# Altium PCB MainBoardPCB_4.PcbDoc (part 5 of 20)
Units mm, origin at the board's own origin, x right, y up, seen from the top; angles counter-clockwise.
Board outline 333.63 x 349.38 mm, 16 copper layers (L1, L2 (GND), L3 (Sign), L4 (GND), L5 (Sign), L6 (PWR/GND), L7(PWR/GND), L8 (Plane_GND), L9 (PWR/GND), L10 (PWR/GND), L11 (PWR/GND), L12 (Sign), L13 (GND), L14 (Sign), L15 (GND), L16), stack 2.502 mm thick; 2205 components, 1648 nets, 8314 pads, 3172 vias.
Unrouted connection lines stored in the file: 5141.
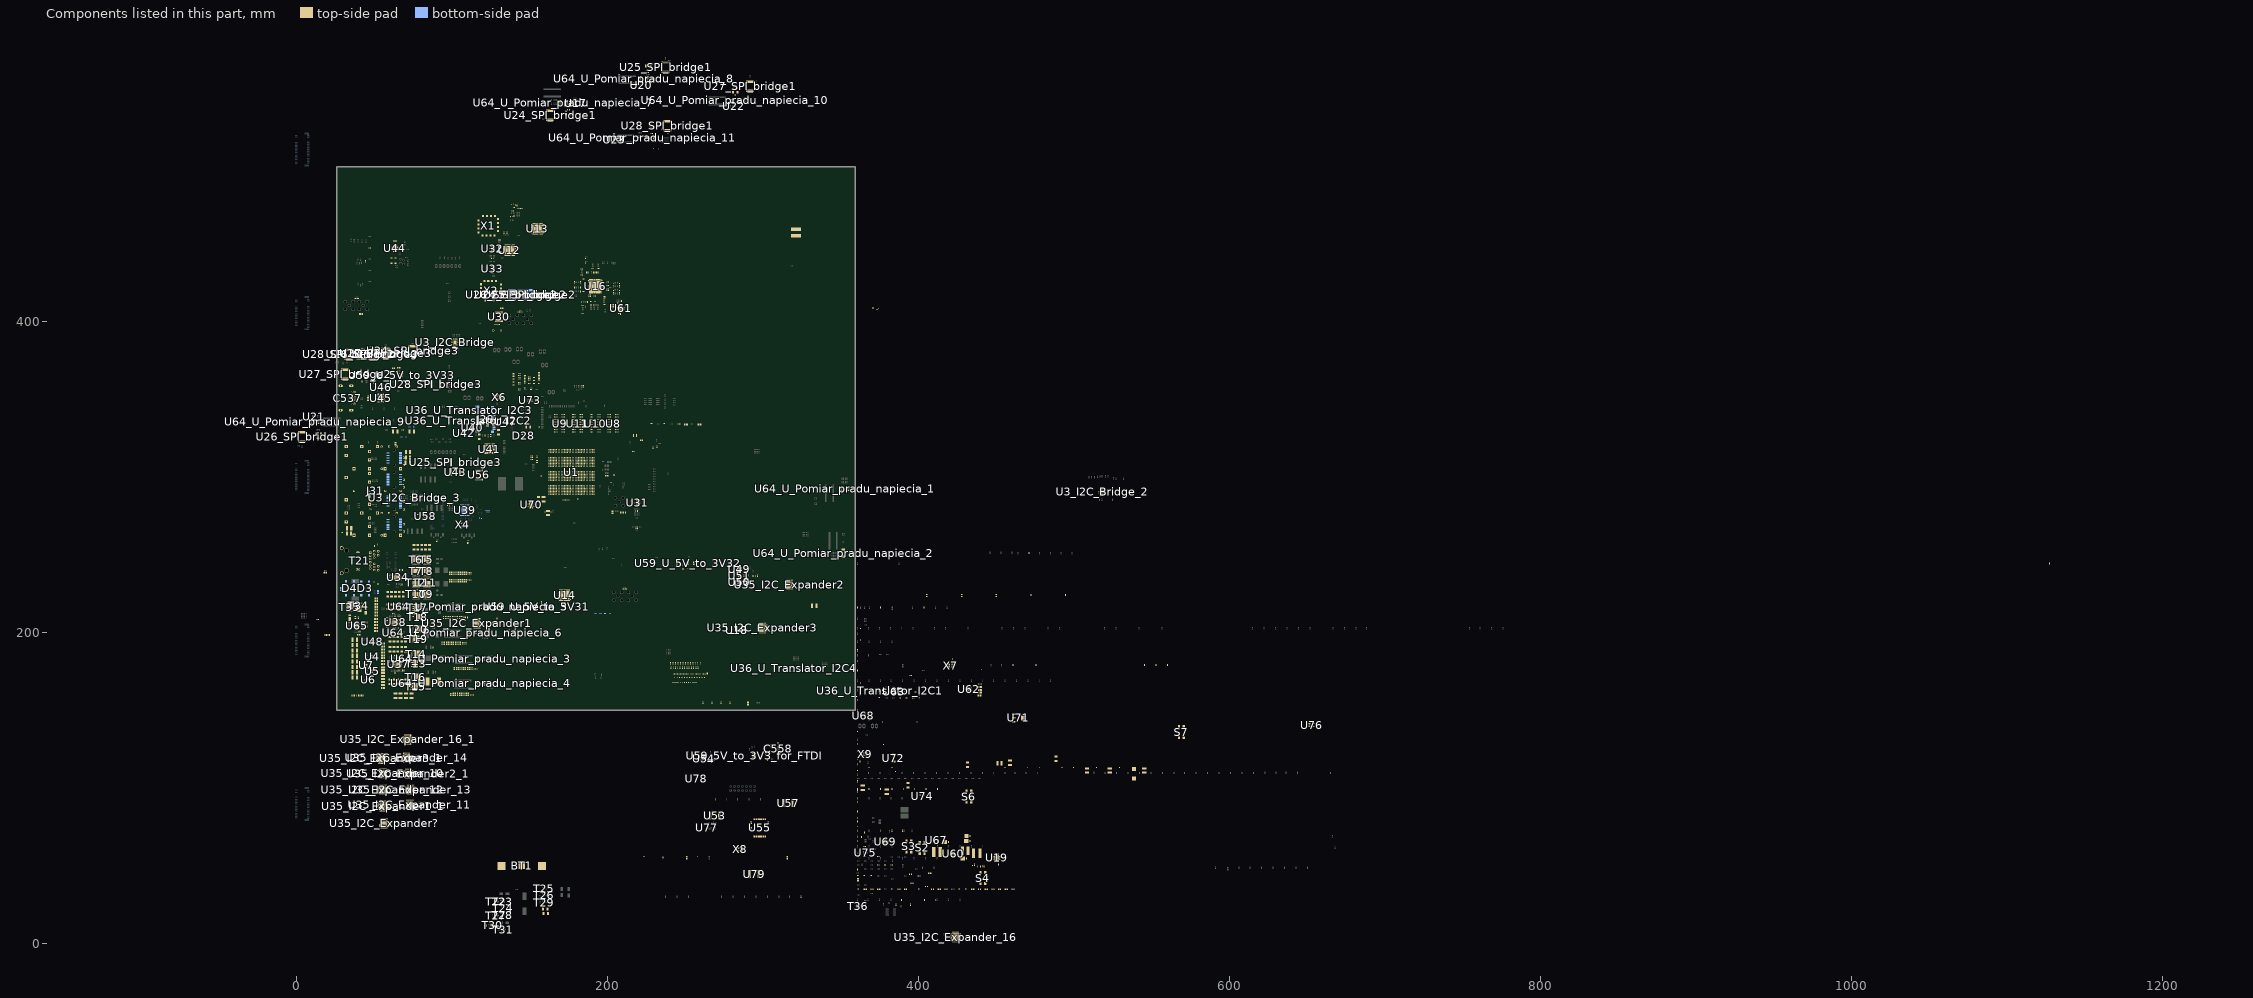
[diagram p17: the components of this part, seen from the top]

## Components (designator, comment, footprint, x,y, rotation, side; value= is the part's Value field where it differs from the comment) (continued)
T5 "BSC080N03LSG" BSC080N03LS 83.977,246.623 r90 top
T6 "BSC080N03LSG" BSC080N03LS 76.977,246.623 r90 top locked
T7 "BSC030N03LS-G" BSC030N03LS 76.977,239.389 r90 top
T8 "BSC030N03LS-G" BSC030N03LS 83.977,239.389 r90 top
T9 "BSC080N03LSG" BSC080N03LS 83.977,224.601 r270 top
T10 "BSC080N03LSG" BSC080N03LS 76.983,224.601 r270 top
T11 "BSC030N03LS-G" BSC030N03LS 83.977,231.864 r270 top
T12 "BSC030N03LS-G" BSC030N03LS 76.977,231.864 r270 top
T13 "BSC080N03LSG" BSC080N03LS 77.142,179.908 r180 top
T14 "BSC030N03LS-G" BSC030N03LS 77.114,186.055 r0 top
T15 "BSC080N03LSG" BSC080N03LS 76.889,165.106 r180 top
T16 "BSC030N03LS-G" BSC030N03LS 76.91,171.285 r0 top
T17 "BSC080N03LSG" BSC080N03LS 78.098,215.984 r180 top
T18 "BSC030N03LS-G" BSC030N03LS 78.073,209.702 r0 top
T19 "BSC080N03LSG" BSC080N03LS 78.029,195.651 r180 top
T20 "BSC030N03LS-G" BSC030N03LS 77.974,202.057 r0 top
T21 "7499511440" 7499511440 37.922,246.126 r90 bottom
T22 "IRLML6401TRPBF" IRLML6401PbF 128.638,26.733 r0 top
T23 "IRLML6401TRPBF" IRLML6401PbF 132.715,26.81 r0 top
T24 "SI2342DS-T1-GE3" SI2342DS-T1-GE3 132.905,22.581 r0 top
T25 "SI2342DS-T1-GE3" SI2342DS-T1-GE3 159.55,35.065 r0 top
T26 "SI2342DS-T1-GE3" SI2342DS-T1-GE3 159.461,30.836 r0 top
T27 "IRLML6401TRPBF" IRLML6401PbF 128.524,17.818 r0 top
T28 "SI2342DS-T1-GE3" SI2342DS-T1-GE3 132.601,18.212 r0 top
T29 "SI2342DS-T1-GE3" SI2342DS-T1-GE3 159.55,26.2 r0 top
T30 "IRLML6401TRPBF" IRLML6401PbF 126.263,11.532 r0 top
T31 "SI2342DS-T1-GE3" SI2342DS-T1-GE3 133.096,8.801 r0 top
T34 "RJK0651DPB-00#J5" RJK0651DPB 40.282,216.141 r270 top
T35 "SIJ482DP-T1-GE3" SiJ482DP 34.455,216.179 r90 top
T36 "SI2342DS-T1-GE3" SI2342DS-T1-GE3 361.423,24.028 r0 top
TP1_I2C_Bridge "TestPoint" TestPoint 766.635,73.393 r90 top (schematic designator TP1)
TP1_I2C_Bridge_2 "TestPoint" TestPoint 1231.379,242.418 r90 top (schematic designator TP1)
TP1_I2C_Bridge_3 "TestPoint" TestPoint 775.271,83.629 r90 top (schematic designator TP1)
TP2_I2C_Bridge "TestPoint" TestPoint 743.534,73.393 r90 top (schematic designator TP2)
TP2_I2C_Bridge_2 "TestPoint" TestPoint 1206.233,242.418 r90 top (schematic designator TP2)
TP2_I2C_Bridge_3 "TestPoint" TestPoint 751.662,83.629 r90 top (schematic designator TP2)
TP3_I2C_Bridge "TestPoint" TestPoint 720.42,73.393 r90 top (schematic designator TP3)
TP3_I2C_Bridge_2 "TestPoint" TestPoint 1181.1,242.418 r90 top (schematic designator TP3)
TP3_I2C_Bridge_3 "TestPoint" TestPoint 728.04,83.629 r90 top (schematic designator TP3)
TP4_I2C_Bridge "TestPoint" TestPoint 697.319,73.393 r90 top (schematic designator TP4)
TP4_I2C_Bridge_2 "TestPoint" TestPoint 1155.967,242.418 r90 top (schematic designator TP4)
TP4_I2C_Bridge_3 "TestPoint" TestPoint 704.418,83.629 r90 top (schematic designator TP4)
TP5_I2C_Bridge "TestPoint" TestPoint 674.205,73.393 r90 top (schematic designator TP5)
TP5_I2C_Bridge_2 "TestPoint" TestPoint 1104.151,242.418 r90 top (schematic designator TP5)
TP5_I2C_Bridge_3 "TestPoint" TestPoint 680.809,83.629 r90 top (schematic designator TP5)
TP6_I2C_Bridge "TestPoint" TestPoint 651.104,73.393 r90 top (schematic designator TP6)
TP6_I2C_Bridge_2 "TestPoint" TestPoint 1079.017,242.418 r90 top (schematic designator TP6)
TP6_I2C_Bridge_3 "TestPoint" TestPoint 657.187,83.629 r90 top (schematic designator TP6)
TP7_I2C_Bridge_2 "TestPoint" TestPoint 898.22,242.418 r90 top (schematic designator TP7)
TP8_I2C_Bridge "TestPoint" TestPoint 627.99,73.393 r90 top (schematic designator TP8)
TP8_I2C_Bridge_2 "TestPoint" TestPoint 1053.871,242.418 r90 top (schematic designator TP8)
TP8_I2C_Bridge_3 "TestPoint" TestPoint 633.578,83.629 r90 top (schematic designator TP8)
TP9_I2C_Bridge "TestPoint" TestPoint 604.888,73.393 r90 top (schematic designator TP9)
TP9_I2C_Bridge_2 "TestPoint" TestPoint 1028.738,242.418 r90 top (schematic designator TP9)
TP9_I2C_Bridge_3 "TestPoint" TestPoint 609.956,83.629 r90 top (schematic designator TP9)
TP10_I2C_Bridge "TestPoint" TestPoint 580.504,73.393 r90 top (schematic designator TP10)
TP10_I2C_Bridge_2 "TestPoint" TestPoint 1002.322,242.418 r90 top (schematic designator TP10)
TP10_I2C_Bridge_3 "TestPoint" TestPoint 585.076,83.629 r90 top (schematic designator TP10)
TP11_I2C_Bridge "TestPoint" TestPoint 556.387,73.393 r90 top (schematic designator TP11)
TP11_I2C_Bridge_2 "TestPoint" TestPoint 976.173,242.418 r90 top (schematic designator TP11)
TP11_I2C_Bridge_3 "TestPoint" TestPoint 560.438,83.629 r90 top (schematic designator TP11)
TP12_I2C_Bridge_2 "TestPoint" TestPoint 949.769,242.418 r90 top (schematic designator TP12)
TP13_I2C_Bridge_2 "TestPoint" TestPoint 923.353,242.418 r90 top (schematic designator TP13)
TP14_I2C_Bridge_2 "TestPoint" TestPoint 871.804,242.418 r90 top (schematic designator TP14)
TP15_I2C_Bridge "TestPoint" TestPoint 387.007,232.181 r90 top (schematic designator TP15)
TP15_I2C_Bridge_2 "TestPoint" TestPoint 845.401,242.418 r90 top (schematic designator TP15)
TP15_I2C_Bridge_3 "TestPoint" TestPoint 362.636,74.905 r90 top (schematic designator TP15)
TP16_I2C_Bridge "TestPoint" TestPoint 362.636,232.181 r90 top (schematic designator TP16)
TP16_I2C_Bridge_2 "TestPoint" TestPoint 818.985,242.418 r90 top (schematic designator TP16)
TP16_I2C_Bridge_3 "TestPoint" TestPoint 521.818,103.632 r90 top (schematic designator TP16)
TP17_I2C_Bridge "TestPoint" TestPoint 387.007,64.668 r90 top (schematic designator TP17)
TP17_I2C_Bridge_2 "TestPoint" TestPoint 792.582,242.418 r90 top (schematic designator TP17)
TP17_I2C_Bridge_3 "TestPoint" TestPoint 500.431,105.664 r90 top (schematic designator TP17)
TP18_I2C_Bridge "TestPoint" TestPoint 379.324,59.372 r90 top (schematic designator TP18)
TP18_I2C_Bridge_2 "TestPoint" TestPoint 766.166,242.418 r90 top (schematic designator TP18)
TP18_I2C_Bridge_3 "TestPoint" TestPoint 506.4,116.599 r90 top (schematic designator TP18)
TP19 "TestPoint" TestPoint 371.297,22.606 r0 top
TP20 "TestPoint" TestPoint 365.925,19.431 r0 top
TP33 "TestPoint" TestPoint 441.947,64.834 r0 top
TP34 "TestPoint" TestPoint 661.441,201.346 r0 top
TP35 "TestPoint" TestPoint 609.879,201.346 r0 top
TP36 "TestPoint" TestPoint 551.447,201.346 r0 top
TP37 "TestPoint" TestPoint 536.715,201.346 r0 top
TP38 "TestPoint" TestPoint 478.282,201.346 r0 top
TP39 "TestPoint" TestPoint 448.818,201.346 r0 top
TP40 "TestPoint" TestPoint 441.452,201.346 r0 top
TP41 "TestPoint" TestPoint 427.152,201.346 r0 top
TP42 "TestPoint" TestPoint 405.308,201.346 r0 top
TP43 "TestPoint" TestPoint 436.791,192.621 r0 top
TP44 "TestPoint" TestPoint 429.425,192.621 r0 top
TP45 "TestPoint" TestPoint 422.059,192.621 r0 top
TP46 "TestPoint" TestPoint 414.706,192.621 r0 top
TP47 "TestPoint" TestPoint 407.34,192.621 r0 top
TP48 "TestPoint" TestPoint 399.974,192.621 r0 top
TP49 "TestPoint" TestPoint 392.608,192.621 r0 top
TP50_SPI_bridge2 "TestPoint" TestPoint 239.789,400.736 r0 top (schematic designator TP50)
TP50_SPI_bridge3 "TestPoint" TestPoint 513.207,104.102 r90 top (schematic designator TP50)
TP51_SPI_bridge2 "TestPoint" TestPoint 235.217,390.855 r0 top (schematic designator TP51)
TP51_SPI_bridge3 "TestPoint" TestPoint 488.328,104.102 r90 top (schematic designator TP51)
TP52_SPI_bridge2 "TestPoint" TestPoint 240.805,395.199 r0 top (schematic designator TP52)
TP52_SPI_bridge3 "TestPoint" TestPoint 463.182,104.102 r90 top (schematic designator TP52)
TP53_SPI_bridge1 "TestPoint" TestPoint 436.524,351.409 r90 top (schematic designator TP53)
TP53_SPI_bridge2 "TestPoint" TestPoint 231.318,402.933 r0 top (schematic designator TP53)
TP53_SPI_bridge3 "TestPoint" TestPoint 438.048,104.102 r90 top (schematic designator TP53)
TP54_SPI_bridge2 "TestPoint" TestPoint 238.938,408.292 r0 top (schematic designator TP54)
TP55_SPI_bridge2 "TestPoint" TestPoint 250.114,409.873 r0 top (schematic designator TP55)
TP56_SPI_bridge1 "TestPoint" TestPoint 411.899,351.409 r90 top (schematic designator TP56)
TP56_SPI_bridge2 "TestPoint" TestPoint 247.688,404.228 r0 top (schematic designator TP56)
TP56_SPI_bridge3 "TestPoint" TestPoint 412.915,361.645 r90 top (schematic designator TP56)
TP57_SPI_bridge1 "TestPoint" TestPoint 387.261,351.409 r90 top (schematic designator TP57)
TP57_SPI_bridge2 "TestPoint" TestPoint 256.083,410.096 r0 top (schematic designator TP57)
TP57_SPI_bridge3 "TestPoint" TestPoint 387.769,361.645 r90 top (schematic designator TP57)
TP58_SPI_bridge1 "TestPoint" TestPoint 417.716,94.221 r90 top (schematic designator TP58)
TP58_SPI_bridge2 "TestPoint" TestPoint 247.282,398.082 r0 top (schematic designator TP58)
TP58_SPI_bridge3 "TestPoint" TestPoint 387.769,95.377 r90 top (schematic designator TP58)
TP59_SPI_bridge1 "TestPoint" TestPoint 362.636,351.409 r90 top (schematic designator TP59)
TP59_SPI_bridge2 "TestPoint" TestPoint 254.734,404 r0 top (schematic designator TP59)
TP59_SPI_bridge3 "TestPoint" TestPoint 362.636,361.645 r90 top (schematic designator TP59)
TP60_U_Translator_I2C1 "TestPoint" TestPoint 253.441,398.64 r0 top (schematic designator TP60)
TP60_U_Translator_I2C2 "TestPoint" TestPoint 396.733,117.5 r90 top (schematic designator TP60)
TP60_U_Translator_I2C3 "TestPoint" TestPoint 262.179,409.651 r0 top (schematic designator TP60)
TP60_U_Translator_I2C4 "TestPoint" TestPoint 258.966,398.031 r0 top (schematic designator TP60)
TP61_U_Translator_I2C1 "TestPoint" TestPoint 231.546,408.013 r0 top (schematic designator TP61)
TP61_U_Translator_I2C2 "TestPoint" TestPoint 362.636,371.881 r90 top (schematic designator TP61)
TP61_U_Translator_I2C3 "TestPoint" TestPoint 240.182,388.887 r0 top (schematic designator TP61)
TP61_U_Translator_I2C4 "TestPoint" TestPoint 231.61,398.196 r0 top (schematic designator TP61)
TP62 "TestPoint" TestPoint 539.001,29.273 r0 top
TP63 "TestPoint" TestPoint 531.635,29.273 r0 top
TP64 "TestPoint" TestPoint 524.281,29.273 r0 top
TP65 "TestPoint" TestPoint 516.915,29.273 r0 top
TP66 "TestPoint" TestPoint 509.549,29.273 r0 top
TP67 "TestPoint" TestPoint 502.183,29.273 r0 top
TP68 "TestPoint" TestPoint 494.817,29.273 r0 top
TP69 "TestPoint" TestPoint 487.451,29.273 r0 top
TP70 "TestPoint" TestPoint 480.085,29.273 r0 top
TP71 "TestPoint" TestPoint 473.164,29.273 r0 top
TP72 "TestPoint" TestPoint 465.798,29.273 r0 top
TP73 "TestPoint" TestPoint 473.164,37.998 r0 top
TP74 "TestPoint" TestPoint 465.798,37.998 r0 top
TP75 "TestPoint" TestPoint 458.432,29.273 r0 top
TP76 "TestPoint" TestPoint 451.066,29.273 r0 top
TP77 "TestPoint" TestPoint 443.713,29.273 r0 top
TP78 "TestPoint" TestPoint 436.347,29.273 r0 top
TP79 "TestPoint" TestPoint 428.981,29.273 r0 top
TP80 "TestPoint" TestPoint 421.615,29.273 r0 top
TP81 "TestPoint" TestPoint 414.693,29.273 r0 top
TP82 "TestPoint" TestPoint 408.648,29.489 r0 top
TP83 "TestPoint" TestPoint 399.961,29.273 r0 top
TP84 "TestPoint" TestPoint 392.595,29.273 r0 top
TP85 "TestPoint" TestPoint 385.229,29.273 r0 top
TP86 "TestPoint" TestPoint 377.863,29.273 r0 top
TP87 "TestPoint" TestPoint 370.802,28.854 r0 top
TP88 "TestPoint" TestPoint 402.272,19.914 r0 top
TP91 "TestPoint" TestPoint 370.497,151.397 r0 top
TP92 "TestPoint" TestPoint 363.131,151.397 r0 top
U1 "FBVB900" "FBVB900 XX" 176.897,303.039 r90 top locked
U3_I2C_Bridge "TCA9548" TCA9548 102.07,386.613 r90 top (schematic designator U3)
U3_I2C_Bridge_2 "TCA9548" TCA9548 518.223,290.373 r90 top (schematic designator U3)
U3_I2C_Bridge_3 "TCA9548" TCA9548 75.769,286.567 r90 top (schematic designator U3)
U4 "TPS2121RUXT" TPS212x 48.71,184.321 r270 top
U5 "TPS2121RUXT" TPS212x 48.71,175 r270 top
U6 "FPF2895CUCX" FPF2895C-D 46.21,169.389 r90 top
U7 "FPF2895CUCX" FPF2895C-D 45.075,178.775 r0 top
U8 "MT40A512M16JY" MT40A512M16JY 203.657,334.06 r180 top locked
U9 "MT40A512M16JY" MT40A512M16JY 169.276,334.06 r180 top locked
U10 "MT40A512M16JY" MT40A512M16JY 192.197,334.06 r180 top locked
U11 "MT40A512M16JY" MT40A512M16JY 180.736,334.06 r180 top locked
U12 "LTC6952" LTC6952 137.046,445.63 r90 top
U13 "LTC6952" LTC6952 155.05,459.542 r90 top
U14 "LTC6952" LTC6952 172.476,223.926 r90 top
U15 "SN74AXC4T774PWR" SN74AXC4T774PWR 41.295,378.993 r90 top
U16 "LMK05028" LMK05028 192.24,422.516 r90 top
U17 "FPF2895CUCX" FPF2895C-D 179.528,540.397 r0 top
U18 "FPF2895CUCX" FPF2895C-D 283.346,201.393 r0 top
U19 "LT3504EUFD#PBF" LT3504 450.431,55.143 r0 top
U20 "FPF2895CUCX" FPF2895C-D 221.847,551.77 r270 top
U21 "FPF2895CUCX" FPF2895C-D 11.167,338.579 r270 top
U22 "FPF2895CUCX" FPF2895C-D 281.268,538.267 r90 top
U23 "FPF2895CUCX" FPF2895C-D 204.448,516.817 r0 top
U24_SPI_bridge1 "SN74AXC4T774PWR" SN74AXC4T774PWR 163.18,532.555 r270 top (schematic designator U24)
U24_SPI_bridge2 "SN74AXC4T774PWR" SN74AXC4T774PWR 144.322,416.997 r90 bottom (schematic designator U24)
U24_SPI_bridge3 "SN74AXC4T774PWR" SN74AXC4T774PWR 74.765,381.025 r90 top (schematic designator U24)
U25_SPI_bridge1 "SN74AXC4T774PWR" SN74AXC4T774PWR 237.53,563.508 r90 top (schematic designator U25)
U25_SPI_bridge2 "SN74AXC4T774PWR" SN74AXC4T774PWR 149.974,416.997 r90 bottom (schematic designator U25)
U25_SPI_bridge3 "SN74AXC4T774PWR" SN74AXC4T774PWR 102.324,309.27 r180 top (schematic designator U25)
U26_SPI_bridge1 "SN74AXC4T774PWR" SN74AXC4T774PWR 3.716,325.679 r270 top (schematic designator U26)
U26_SPI_bridge2 "SN74AXC4T774PWR" SN74AXC4T774PWR 138.671,416.997 r90 bottom (schematic designator U26)
U26_SPI_bridge3 "SN74AXC4T774PWR" SN74AXC4T774PWR 48.984,378.739 r90 top (schematic designator U26)
U27_SPI_bridge1 "SN74AXC4T774PWR" SN74AXC4T774PWR 291.77,551.129 r90 top (schematic designator U27)
U27_SPI_bridge2 "SN74AXC4T774PWR" SN74AXC4T774PWR 31.342,365.912 r90 top (schematic designator U27)
U27_SPI_bridge3 "SN74AXC4T774PWR" SN74AXC4T774PWR 57.366,379.501 r90 top (schematic designator U27)
U28_SPI_bridge1 "SN74AXC4T774PWR" SN74AXC4T774PWR 238.684,525.78 r270 top (schematic designator U28)
U28_SPI_bridge2 "SN74AXC4T774PWR" SN74AXC4T774PWR 33.617,378.739 r90 top (schematic designator U28)
U28_SPI_bridge3 "SN74AXC4T774PWR" SN74AXC4T774PWR 89.624,359.435 r180 top (schematic designator U28)
U30 "DAC1220" DAC1220 130.289,402.9 r90 top
U31 "SI53323-B-GM" SI53323-B-GM 219.267,283.493 r270 top
U32 "SI53323-B-GM" SI53323-B-GM 125.971,446.548 r0 top
U33 "CDCM1802RGTT" CDCM1802RGTT 126.102,433.764 r90 top
U34 "ADP1850ACPZ-R7" ADP1850 65.072,235.389 r0 top
U35_I2C_Expander1 "MCP23017-E/ML" QFN-ML28_N 116.167,205.864 r0 top (schematic designator U35)
U35_I2C_Expander1_1 "MCP23017-E/ML" QFN-ML28_N 55.761,88.333 r90 top (schematic designator U35)
U35_I2C_Expander2 "MCP23017-E/ML" QFN-ML28_N 316.954,230.657 r90 top (schematic designator U35)
U35_I2C_Expander2_1 "MCP23017-E/ML" QFN-ML28_N 72.04,109.182 r90 top (schematic designator U35)
U35_I2C_Expander3 "MCP23017-E/ML" QFN-ML28_N 299.575,202.813 r90 top (schematic designator U35)
U35_I2C_Expander3_1 "MCP23017-E/ML" QFN-ML28_N 54.721,118.886 r90 top (schematic designator U35)
U35_I2C_Expander? "MCP23017-E/ML" QFN-ML28_N 56.421,77.163 r90 top (schematic designator U35)
U35_I2C_Expander_10 "MCP23017-E/ML" QFN-ML28_N 55.646,109.332 r90 top (schematic designator U35)
U35_I2C_Expander_11 "MCP23017-E/ML" QFN-ML28_N 73.005,89.078 r90 top (schematic designator U35)
U35_I2C_Expander_12 "MCP23017-E/ML" QFN-ML28_N 55.646,98.666 r90 top (schematic designator U35)
U35_I2C_Expander_13 "MCP23017-E/ML" QFN-ML28_N 73.292,98.666 r90 top (schematic designator U35)
U35_I2C_Expander_14 "MCP23017-E/ML" QFN-ML28_N 70.942,119.263 r90 top (schematic designator U35)
U35_I2C_Expander_16 "MCP23017-E/ML" QFN-ML28_N 424.072,4.1 r90 top (schematic designator U35)
U35_I2C_Expander_16_1 "MCP23017-E/ML" QFN-ML28_N 71.728,131.106 r90 top (schematic designator U35)
U36_U_Translator_I2C1 "PCA9306" PCA9306 375.158,162.56 r90 top (schematic designator U36)
U36_U_Translator_I2C2 "PCA9306" PCA9306 110.627,335.941 r0 top (schematic designator U36)
U36_U_Translator_I2C3 "PCA9306" PCA9306 111.214,342.671 r90 top (schematic designator U36)
U36_U_Translator_I2C4 "PCA9306" PCA9306 319.885,176.957 r90 top (schematic designator U36)
U37 "ADP1850ACPZ-R7" ADP1850 65.425,179.567 r0 top
U38 "ADP1850ACPZ-R7" ADP1850 63.703,206.464 r0 top
U39 "DP83867ERGZT" DP83867E 108.299,278.525 r0 bottom
U40 "MCP1727T-ADJE/MF" MCP1727T-ADJE/MF 113.17,331.521 r0 top
U41 "MTFC8GAKAJCN-4MITTR" "MTFC8GAKAJCN-4M IT TR" 124.188,317.841 r270 top locked
U42 "MCP1727T-ADJE/MF" MCP1727T-ADJE/MF 107.539,328.046 r0 top
U43 "SN74AXC4T774PWR" SN74AXC4T774PWR 102.324,303.047 r180 top
U44 "MAX16025TE+T" MAX16025TE+T 63.42,446.853 r0 top
U45 "USB3320C-EZK-TR" USB3320 54.331,350.685 r0 top
U46 "FPF2895CUCX" FPF2895C-D 54.445,357.645 r0 top
U47 "IP4856CX25/CZ" IP4856CX25/C 134.729,335.404 r180 bottom locked
U48 "TPS2121RUXT" TPS212x 48.677,193.983 r270 top
U49 "MCP1727T-ADJE/MF" MCP1727T-ADJE/MF 284.958,240.682 r0 top
U50 "MCP1727T-ADJE/MF" MCP1727T-ADJE/MF 284.831,232.104 r0 top
U51 "MCP1727T-ADJE/MF" MCP1727T-ADJE/MF 284.958,236.364 r0 top
U53 "SN74AXC4T774PWR" SN74AXC4T774PWR 269.029,82.182 r0 top
U54 "93LC56BT-I/OT" 93LC56BT 261.971,118.631 r0 top
U55 "FT4232HL-REEL" FT4232HL 297.904,74.295 r0 top
U56 "SN74AXC4T774PWR" SN74AXC4T774PWR 117.335,301.231 r270 top
U57 "SN74AXC4T774PWR" SN74AXC4T774PWR 316.179,90.183 r0 top
U58 "ISM330DHCXTR" ISM330DHCXL 83.007,274.777 r0 top
U59_5V_to_3V3_for_FTDI "MCP1727T-ADJE/MF" MCP1727T-ADJE/MF 294.348,120.688 r90 top (schematic designator U59)
U59_U_5V_to_3V31 "MCP1727T-ADJE/MF" MCP1727T-ADJE/MF 154.362,216.491 r0 top (schematic designator U59)
U59_U_5V_to_3V32 "MCP1727T-ADJE/MF" MCP1727T-ADJE/MF 251.841,244.386 r180 top (schematic designator U59)
U59_U_5V_to_3V33 "MCP1727T-ADJE/MF" MCP1727T-ADJE/MF 67.78,365.404 r0 top (schematic designator U59)
U60 "ADP1741ACPZ-R7" ADP1752_1753/ADP1740_1741 422.354,57.672 r0 top
U61 "TPS7A8801RTJT" TPS7A88 208.496,408.446 r180 top
U62 "LT3042EDD#PBF" LT3042 432.308,163.576 r0 top
U63 "MAX3051EKA+T" "MAX3051EKA+T SOT23" 384.289,161.823 r0 top
U64_U_Pomiar_pradu_napiecia_1 "INA226AIDGSR" INA226 352.727,292.236 r0 top (schematic designator U64)
U64_U_Pomiar_pradu_napiecia_2 "INA226AIDGSR" INA226 351.752,250.85 r90 top (schematic designator U64)
U64_U_Pomiar_pradu_napiecia_3 "INA226AIDGSR" INA226 118.478,183.159 r180 top (schematic designator U64)
U64_U_Pomiar_pradu_napiecia_4 "INA226AIDGSR" INA226 118.681,167.127 r180 top (schematic designator U64)
U64_U_Pomiar_pradu_napiecia_5 "INA226AIDGSR" INA226 116.548,216.393 r180 top (schematic designator U64)
U64_U_Pomiar_pradu_napiecia_6 "INA226AIDGSR" INA226 113.005,199.771 r180 top (schematic designator U64)
U64_U_Pomiar_pradu_napiecia_7 "INA226AIDGSR" INA226 171.775,540.697 r0 top (schematic designator U64)
U64_U_Pomiar_pradu_napiecia_8 "INA226AIDGSR" INA226 223.444,556.142 r180 top (schematic designator U64)
U64_U_Pomiar_pradu_napiecia_9 "INA226AIDGSR" INA226 12.002,335.331 r0 top (schematic designator U64)
U64_U_Pomiar_pradu_napiecia_10 "INA226AIDGSR" INA226 281.823,542.12 r180 top (schematic designator U64)
U64_U_Pomiar_pradu_napiecia_11 "INA226AIDGSR" INA226 222.428,518.16 r180 top (schematic designator U64)
U65 "MAX17557ATP+" MAX17557 38.76,204.318 r90 top
U67 "LM3880MFE-1AF/NOPB" LM3880-Q1 411.353,66.332 r0 top
U68 "LM3880MFE-1AF/NOPB" LM3880-Q1 364.426,146.444 r0 top
U69 "ADP1741ACPZ-R7" ADP1752_1753/ADP1740_1741 378.732,65.251 r0 top
U70 "TPS7A8801RTJT" TPS7A88 150.914,282.003 r0 top
U71 "UA78M08CDCYR" UA78M 464.337,144.958 r0 top
U72 "INA226AIDGSR" INA226 383.997,119.189 r90 top
U73 "ST1L08SPUR" ST1L08 150.244,349.234 r0 top
U74 "SN74LVC1G08DBVR" SN74LVC1G08DBVR 402.488,94.602 r0 top
U75 "ESDCAN02-2BWY" ESDCAN02-2BWY 365.852,58.141 r0 top
U76 "SN74LVC1G08DBVR" SN74LVC1G08DBVR 652.831,140.335 r0 top
U77 "NC7WZ07FHX" NC7WZ07FHX 263.949,74.317 r90 top
U78 "NC7WZ07FHX" NC7WZ07FHX 257.238,105.88 r90 top
U79 "SN74AXC4T774PWR" SN74AXC4T774PWR 294.373,44.602 r0 top
X1 "OSC CRO 2000-2000 MHZ SMD .5X.5" CVCO55CW 117.081,455.097 r0 top
X2 "OSC VCO 490-540MHZ SMD .5X.5\"" CVCO55CW 131.559,413.314 r90 top
X3 "2.4576MHz" Crystal 131.613,394.137 r180 top
X4 "FA-23825.0000MB-C3" FA-23825.0000MB-C3 107.086,269.076 r180 bottom
X5 "32.768kHz" FC-135R/FC-135 149.073,332.105 r0 top
X6 "510CCA50M0000BAG" Si510 130.504,351.091 r270 top
X7 "TSX-322524.0000MF15X-AC6" "TSX-3225 24.0000MF15X-AC6" 420.789,178.498 r0 top
X8 "ECS-120-8-33-RWY-TR" ECS-120-8-33-RWY-TR 285.42,60.389 r0 top
X9 "SIT1602BI-12-33E-48.000000G" SiT1602B 365.762,121.718 r0 top

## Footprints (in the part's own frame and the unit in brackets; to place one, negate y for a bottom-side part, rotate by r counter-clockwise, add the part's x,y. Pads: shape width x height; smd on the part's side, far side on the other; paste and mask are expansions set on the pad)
93LC56BT [mm] "SOT-23-6, 6-Leads, Body 2,90x1,55mm, Pitch 0,95mm, IPC High Density"
  rect 1.1x0.6 smd: 1(-1.4,0.95) 2(-1.4,0) 3(-1.4,-0.95) 4(1.4,-0.95) 5(1.4,0) 6(1.4,0.95)
  silkscreen extent -1.52,-1.55 0.5,1.92, body extent -1.35,-1.55 1.35,1.55, height 1.45
2007132 [mm] "SFP Connector"
  rect 0.5x2 smd: 1(3.725,21.8) 2(4.525,21.8) 3(5.325,21.8) 4(6.125,21.8) 5(6.925,21.8) 6(7.725,21.8) 7(8.525,21.8) 8(9.325,21.8) 9(10.125,21.8) 10(10.925,21.8) 11(10.525,30) 12(9.725,30) 13(8.925,30) 14(8.125,30) 15(7.325,30) 16(6.525,30) 17(5.725,30) 18(4.925,30) 19(4.125,30) 20(3.325,30) 21(17.975,21.8) 22(18.775,21.8) 23(19.575,21.8) 24(20.375,21.8) 25(21.175,21.8) 26(21.975,21.8) 27(22.775,21.8) 28(23.575,21.8) 29(24.375,21.8) 30(25.175,21.8) 31(24.775,30) 32(23.975,30) 33(23.175,30) 34(22.375,30) 35(21.575,30) 36(20.775,30) 37(19.975,30) 38(19.175,30) 39(18.375,30) 40(17.565,29.997) 41(32.225,21.8) 42(33.025,21.8) 43(33.825,21.8) 44(34.625,21.8) 45(35.425,21.8) 46(36.225,21.8) 47(37.025,21.8) 48(37.825,21.8) 49(38.625,21.8) 50(39.425,21.8) 51(39.025,30) 52(38.225,30) 53(37.425,30) 54(36.625,30) 55(35.825,30) 56(35.025,30) 57(34.225,30) 58(33.425,30) 59(32.625,30) 60(31.825,30) 61(46.475,21.8) 62(47.275,21.8) 63(48.075,21.8) 64(48.875,21.8) 65(49.675,21.8) 66(50.475,21.8) 67(51.275,21.8) 68(52.075,21.8) 69(52.875,21.8) 70(53.675,21.8) 71(53.275,30) 72(52.475,30) 73(51.675,30) 74(50.875,30) 75(50.075,30) 76(49.275,30) 77(48.475,30) 78(47.675,30) 79(46.875,30) 80(46.075,30)
  rect 2x2 hole 1.05: SH1(0,0) SH2(8.575,-5) SH3(14.25,-5) SH4(0,10) SH5(5.675,10) SH6(11.075,10) SH7(14.25,15) SH8(0,20) SH9(0,30) SH10(14.25,5) SH13(19.925,10) SH14(25.325,10) SH17(22.825,-5) SH20(34.175,10) SH21(39.575,10) SH22(42.75,10) SH23(42.75,0) SH24(37.075,-5) SH25(42.75,20) SH26(42.75,30) SH29(57,15) SH30(57,5) SH31(57,-5) SH32(48.425,10) SH33(53.825,10) SH34(51.325,-5)
  round 1.458 hole 0.95: SH11(14.25,22.5) SH12(14.25,27.5) SH15(28.5,10) SH16(28.5,0) SH18(28.5,20) SH19(28.5,30) SH27(57,27.5) SH28(57,22.5) SH35(0,17.8) SH36(2.325,32.1) SH37(7.125,32.1) SH38(14.25,17.8) SH39(16.575,32.1) SH40(21.375,32.1) SH41(30.825,32.1) SH42(35.625,32.1) SH43(45.075,32.1) SH44(49.875,32.1) SH45(42.75,17.8) SH46(57,17.8)
  round 1.55 hole 1.55: ""(2.325,25.9) ""(16.575,25.9) ""(26.175,25.9) ""(30.825,25.9) ""(40.425,25.9) ""(45.075,25.9) ""(54.675,25.9)
  round 1.55 hole 1.55 unplated: ""(11.925,25.9)
  Keep-Out Layer region: -1.001,17.3 58,17.3 58,-9.514 -1.001,-9.514
  Keep-Out Layer region: 13.255,31.8 15.25,31.8 15.25,17.306 13.255,17.306
  Keep-Out Layer region: 27.544,31.8 29.5,31.8 29.5,17.328 27.544,17.328
  Keep-Out Layer region: 41.817,31.8 43.75,31.8 43.75,17.328 41.817,17.328
  Keep-Out Layer region: -1.002,31.8 1,31.8 1,17.334 -1.002,17.334
  Keep-Out Layer region: 56.018,31.8 58,31.8 58,17.305 56.018,17.305
  Keep-Out Layer region: -1.001,32.8 3.305,32.8 3.305,31.833 -1.001,31.833
  Keep-Out Layer region: 53.775,32.8 58,32.8 58,31.848 53.775,31.848
  Keep-Out Layer region: 11.207,32.8 17.31,32.8 17.31,31.849 11.207,31.849
  Keep-Out Layer region: 25.472,32.8 31.56,32.8 31.56,31.84 25.472,31.84
  Keep-Out Layer region: 39.72,32.8 45.81,32.8 45.81,31.824 39.72,31.824
  Keep-Out Layer region: -1.002,17.3 58,17.3 58,-9.517 -1.002,-9.517
  Keep-Out Layer region: 13.269,31.8 15.25,31.8 15.25,17.324 13.269,17.324
  Keep-Out Layer region: 27.554,31.8 29.5,31.8 29.5,17.334 27.554,17.334
  Keep-Out Layer region: 41.815,31.8 43.75,31.8 43.75,17.327 41.815,17.327
  Keep-Out Layer region: -1.002,31.8 1,31.8 1,17.328 -1.002,17.328
  Keep-Out Layer region: 56.056,31.8 58,31.8 58,17.317 56.056,17.317
  Keep-Out Layer region: -1,32.8 3.305,32.8 3.305,31.812 -1,31.812
  Keep-Out Layer region: 53.789,32.8 58,32.8 58,31.855 53.789,31.855
  Keep-Out Layer region: 11.205,32.8 17.31,32.8 17.31,31.843 11.205,31.843
  Keep-Out Layer region: 25.485,32.8 31.56,32.8 31.56,31.857 25.485,31.857
  Keep-Out Layer region: 39.745,32.8 45.81,32.8 45.81,31.844 39.745,31.844
  Keep-Out Layer region: -1.001,17.3 58,17.3 58,-9.514 -1.001,-9.514
  Keep-Out Layer region: 13.255,31.8 15.25,31.8 15.25,17.306 13.255,17.306
  Keep-Out Layer region: 27.544,31.8 29.5,31.8 29.5,17.328 27.544,17.328
  Keep-Out Layer region: 41.817,31.8 43.75,31.8 43.75,17.328 41.817,17.328
  Keep-Out Layer region: -1.002,31.8 1,31.8 1,17.334 -1.002,17.334
  Keep-Out Layer region: 56.018,31.8 58,31.8 58,17.305 56.018,17.305
  Keep-Out Layer region: -1.001,32.8 3.305,32.8 3.305,31.833 -1.001,31.833
  Keep-Out Layer region: 53.775,32.8 58,32.8 58,31.848 53.775,31.848
  Keep-Out Layer region: 11.207,32.8 17.31,32.8 17.31,31.849 11.207,31.849
  Keep-Out Layer region: 25.472,32.8 31.56,32.8 31.56,31.84 25.472,31.84
  Keep-Out Layer region: 39.72,32.8 45.81,32.8 45.81,31.824 39.72,31.824
  Keep-Out Layer region: -1.002,17.3 58,17.3 58,-9.517 -1.002,-9.517
  Keep-Out Layer region: 13.269,31.8 15.25,31.8 15.25,17.324 13.269,17.324
  Keep-Out Layer region: 27.554,31.8 29.5,31.8 29.5,17.334 27.554,17.334
  Keep-Out Layer region: 41.815,31.8 43.75,31.8 43.75,17.327 41.815,17.327
  Keep-Out Layer region: -1.002,31.8 1,31.8 1,17.328 -1.002,17.328
  Keep-Out Layer region: 56.056,31.8 58,31.8 58,17.317 56.056,17.317
  Keep-Out Layer region: -1,32.8 3.305,32.8 3.305,31.812 -1,31.812
  Keep-Out Layer region: 53.789,32.8 58,32.8 58,31.855 53.789,31.855
  Keep-Out Layer region: 11.205,32.8 17.31,32.8 17.31,31.843 11.205,31.843
  Keep-Out Layer region: 25.485,32.8 31.56,32.8 31.56,31.857 25.485,31.857
  Keep-Out Layer region: 39.745,32.8 45.81,32.8 45.81,31.844 39.745,31.844
  Keep-Out Layer region: -1.001,17.3 58,17.3 58,-9.514 -1.001,-9.514
  Keep-Out Layer region: 13.255,31.8 15.25,31.8 15.25,17.306 13.255,17.306
  Keep-Out Layer region: 27.544,31.8 29.5,31.8 29.5,17.328 27.544,17.328
  Keep-Out Layer region: 41.817,31.8 43.75,31.8 43.75,17.328 41.817,17.328
  Keep-Out Layer region: -1.002,31.8 1,31.8 1,17.334 -1.002,17.334
  Keep-Out Layer region: 56.018,31.8 58,31.8 58,17.305 56.018,17.305
  Keep-Out Layer region: -1.001,32.8 3.305,32.8 3.305,31.833 -1.001,31.833
  Keep-Out Layer region: 53.775,32.8 58,32.8 58,31.848 53.775,31.848
  Keep-Out Layer region: 11.207,32.8 17.31,32.8 17.31,31.849 11.207,31.849
  Keep-Out Layer region: 25.472,32.8 31.56,32.8 31.56,31.84 25.472,31.84
  Keep-Out Layer region: 39.72,32.8 45.81,32.8 45.81,31.824 39.72,31.824
  Keep-Out Layer region: -1.002,17.3 58,17.3 58,-9.517 -1.002,-9.517
  Keep-Out Layer region: 13.269,31.8 15.25,31.8 15.25,17.324 13.269,17.324
  Keep-Out Layer region: 27.554,31.8 29.5,31.8 29.5,17.334 27.554,17.334
  Keep-Out Layer region: 41.815,31.8 43.75,31.8 43.75,17.327 41.815,17.327
  Keep-Out Layer region: -1.002,31.8 1,31.8 1,17.328 -1.002,17.328
  Keep-Out Layer region: 56.056,31.8 58,31.8 58,17.317 56.056,17.317
  Keep-Out Layer region: -1,32.8 3.305,32.8 3.305,31.812 -1,31.812
  Keep-Out Layer region: 53.789,32.8 58,32.8 58,31.855 53.789,31.855
  Keep-Out Layer region: 11.205,32.8 17.31,32.8 17.31,31.843 11.205,31.843
  Keep-Out Layer region: 25.485,32.8 31.56,32.8 31.56,31.857 25.485,31.857
  Keep-Out Layer region: 39.745,32.8 45.81,32.8 45.81,31.844 39.745,31.844
  silkscreen extent 0,-9.5 57.25,32.57, body extent -0.97,-16.49 58.08,32.49, height 10.62
79523141 [mm] "Battery Holder, Battery Type: 2016,2020,2025,2032"
  rect 5.2x5.2 smd: 1(-12.95,0) 1(12.95,0)
  rect 4x4 smd: 2(0,0)
  silkscreen extent -10.55,-10.5 10.55,9.3, body extent -15.25,-10.5 15.25,9.3, height 4
7499511440 [mm] "LAN Transformer, body 33.02x17mm"
  rect 1.4x1.4 hole 0.89: 1(5.075,9.63)
  round 1.4 hole 0.89: 2(3.045,9.63) 3(1.015,9.63) 4(-1.015,9.63) 5(-3.045,9.63) 6(-5.075,9.63) 7(6.09,12.17) 8(4.06,12.17) 9(2.03,12.17) 10(-2.03,12.17) 11(-4.06,12.17) 12(-6.09,12.17)
  oval 1.4x1.25 hole 0.89: 13(5.59,2.51) 14(-5.59,2.51) 15(5.59,1.05) 16(-5.59,1.05)
  round 1.52 hole 1.02: 17(6.095,14.71) 18(3.555,14.71) 19(-3.555,14.71) 20(-6.095,14.71)
  round 2.8 hole 2.8 unplated: MH1(-6.35,-5.61) MH2(6.35,-5.61)
  round 2.4 hole 1.57: S1(-8.065,-8.79) S2(8.065,-8.79)
  silkscreen extent -10.72,-16.51 10.72,16.51, body extent -10.8,-16.51 10.8,16.51, height 16.21
430181038816 [mm] "Tact Switch, SMD, body 4.5x4.5mm"
  rect 2x1.4 smd: 1(-3.5,1.5) 2(3.5,1.5) 3(-3.5,-1.5) 4(3.5,-1.5)
  silkscreen extent -2.25,-2.25 2.25,2.25, body extent -3.75,-2.25 3.75,2.25, height 3.8
614105150721 [mm] "WR-COM_USB_Micro Type B_Vertical_THT Micro Type B Vertical THT"
  round 0.94 hole 0.44: 1(-1.3,0) 2(-0.65,-1) 3(0,0) 4(0.65,-1) 5(1.3,0)
  oval 0.85x1.5 hole 0.35 slot 1 at 90 deg: Z1(-3.575,-0.22) Z2(3.575,-0.22)
  silkscreen extent -3.7,-1.3 3.7,1.05, body extent -3.99,-1.57 4.01,1.33, height 5.62
692121130100 [mm] "Receptacle TH Reverse Offset 0.14mm"
  rect 1.2x1.2 hole 0.7: 1(-4.35,2.43)
  round 1.2 hole 0.7: 2(-6.85,2.43) 3(-8.85,2.43) 4(-11.35,2.43) 5(-11.85,0.93) 6(-9.85,0.93) 7(-7.85,0.93) 8(-5.85,0.93) 9(-3.85,0.93)
  oval 1.4x2.8 hole 0.8 slot 2.3 at 90 deg: Z1(-15.7,-6.8) Z1(-15.7,0) Z1(0,-6.8) Z1(0,0)
  Keep-Out Layer board cut-out: -14.6,-0.2 -1.1,-0.2 -1.1,-12.15 -14.6,-12.15
  Mechanical 1 keep-out lines w0.127: -14.6,-12.15 -1.1,-12.15 -1.1,-0.2 -14.6,-0.2 -14.6,-12.15
  silkscreen extent -15.16,-12.15 -0.53,3.72, body extent -15.85,-12.15 0.15,3.72, height 3.71
693071020811 [mm] "Micro SD Card Connector Push & Push - with Card Detection - 8 Pins"
  rect 0.7x1.9 smd: 1(2.25,7.75) 2(1.15,7.75) 3(0.05,7.75) 4(-1.05,7.75) 5(-2.15,7.75) 6(-3.25,7.75) 7(-4.35,7.75) 8(-5.45,7.75) 9(-6.55,7.75)
  rect 1.7x1.8 smd: 10(-8.1,6.7) 11(7.4,6.7)
  rect 1.4x2.6 smd: 12(-7.85,-2.9) 13(7.85,-2.9)
  round 0.9 hole 0.9 unplated: MH1(-4.95,-3.3)
  oval 1.7x0.9 hole 0.9 slot 1.7 at 0 deg unplated: MH2(3.05,-3.3)
  silkscreen extent -7.35,-7.25 7.35,7.25, body extent -8.2,-7.3 8.2,7.73, height 1.85
744373560068 [mm] "Precision Wire Wound Inductor, 2-Leads, Body 9,70x8,50mm, IPC High Density"
  rect 2.52x5.33 smd: 1(-3.62,0) 2(3.62,0)
  silkscreen extent -5.1,-4.25 5.1,4.25, body extent -4.95,-4.25 4.95,4.25, height 3.1
ADP1752_1753/ADP1740_1741 [mm] "16-Lead Lead Frame Chip Scale Package [LFCSP_WQ]  4 mm × 4 mm Body, Very Very Thin Quad  (CP-16-23)"
  rect 0.6x0.3 smd: 1(-1.675,0.975) 2(-1.675,0.325) 3(-1.675,-0.325) 4(-1.675,-0.975) 9(1.675,-0.975) 10(1.675,-0.325) 11(1.675,0.325) 12(1.675,0.975)
  rect 0.3x0.6 smd: 5(-0.975,-1.675) 6(-0.325,-1.675) 7(0.325,-1.675) 8(0.975,-1.675) 13(0.975,1.675) 14(0.325,1.675) 15(-0.325,1.675) 16(-0.975,1.675)
  rect 2.1x2.1 smd: 17(0,0)
  silkscreen extent -2.82,-2.05 2.05,2.05, body extent -2.05,-2.05 2.05,2.05, height 0.8
ADP1850 [mm] "32-Lead Lead Frame Chip Scale Package [LFCSP] 5 mm × 5 mm Body and 0.75 mm Package Height (CP-32-12)"
  rect 0.4x0.25 smd: 1(-2.25,1.75) 2(-2.25,1.25) 3(-2.25,0.75) 4(-2.25,0.25) 5(-2.25,-0.25) 6(-2.25,-0.75) 7(-2.25,-1.25) 8(-2.25,-1.75) 17(2.25,-1.75) 18(2.25,-1.25) 19(2.25,-0.75) 20(2.25,-0.25) 21(2.25,0.25) 22(2.25,0.75) 23(2.25,1.25) 24(2.25,1.75)
  rect 0.25x0.4 smd: 9(-1.75,-2.25) 10(-1.25,-2.25) 11(-0.75,-2.25) 12(-0.25,-2.25) 13(0.25,-2.25) 14(0.75,-2.25) 15(1.25,-2.25) 16(1.75,-2.25) 25(1.75,2.25) 26(1.25,2.25) 27(0.75,2.25) 28(0.25,2.25) 29(-0.25,2.25) 30(-0.75,2.25) 31(-1.25,2.25) 32(-1.75,2.25)
  rect 3.6x3.6 smd paste-3: 33(0,0)
  silkscreen extent -3.27,-2.5 2.5,2.5, body extent -2.5,-2.5 2.5,2.5, height 0.8
BAS40-04-TP [mm] "SOT23, 3-Leads, Body 2,92x2,37mm, Pitch 0,90mm, IPC High Density"
  rect 0.9x0.8 smd: 1(-1,0.95) 2(-1,-0.95) 3(1,0)
  silkscreen extent -1.12,-1.5 0.7,1.98, body extent -1.32,-1.52 1.32,1.52, height 1.12
BAT54T1G [mm] "SOD-123  CASE 425-04"
  rect 0.91x1.22 smd: 1(-1.635,0) 2(1.635,0)
  silkscreen extent -2.04,0.86 -1.94,0.96, body extent -1.86,-0.9 1.86,0.9, height 1.35
Battery [mm]
  rect 0.5x1.8 smd: 1(1,0) 2(-1,0)
  Keep-Out Layer circle w0.254: c0,6.858 r4.906
  silkscreen extent -4.86,-2.5 4.91,11.73
BSC030N03LS [mm] "PG-TDSON-8-1"
  rect 0.85x0.6 smd: 1(-2.9,1.905) 2(-2.9,0.635) 3(-2.9,-0.635) 4(-2.9,-1.905)
  rect 0.8x0.6 smd: 5(2.925,-1.905) 6(2.925,-0.635) 7(2.925,0.635) 8(2.925,1.905)
  rect 3.762x4.41 smd paste-2: ""(0.662,0)
  silkscreen extent -3.77,-2.89 3.32,2.94, body extent -3.32,-2.75 3.32,2.75, height 1.1
BSC080N03LS [mm] "PG-TDSON-8-5"
  rect 0.85x0.6 smd: 1(-2.9,1.905) 2(-2.9,0.635) 3(-2.9,-0.635) 4(-2.9,-1.905)
  rect 0.8x0.6 smd: 5(2.925,-1.905) 6(2.925,-0.635) 7(2.925,0.635) 8(2.925,1.905)
  rect 3.762x4.41 smd paste-2: ""(0.662,0)
  silkscreen extent -3.77,-2.89 3.32,2.94, body extent -3.32,-2.75 3.32,2.75, height 1.1
"CAP 0201/0603 RF" [mm] "Chip Capacitor, 2-Leads, Body 0.60x0.30mm, IPC High Density"
  rect 0.3x0.32 smd: 1(-0.26,0) 2(0.26,0)
  silkscreen extent -0.57,-0.33 0.58,0.33, body extent -0.3,-0.15 0.3,0.15, height 0.3
"CAP 0402/1005 RF" [mm] "Chip Capacitor, 2-Leads, Body 1.02x0.51mm, IPC High Density"
  rect 0.55x0.54 smd: 1(-0.39,0) 2(0.39,0)
  silkscreen extent -0.88,-0.45 0.87,0.45, body extent -0.5,-0.26 0.5,0.26, height 0.52
"CAP 0603/1608 RF" [mm] "Chip Capacitor, 2-Leads, Body 1.60x0.80mm, IPC High Density"
  rect 0.8x0.9 smd: 1(-0.625,0) 2(0.625,0)
  silkscreen extent -1.2,-0.62 1.2,0.62, body extent -0.8,-0.41 0.8,0.41, height 0.82
"CAP 0805/2012 RF" [mm] "Chip Capacitor, 2-Leads, Body 2.00x1.20mm, IPC High Density"
  rect 1.1x1.3 smd: 1(-0.7,0) 2(0.7,0)
  silkscreen extent -1.43,-0.82 1.43,0.82, body extent -1,-0.64 1,0.64, height 1.26
"CAP 1206/3216" [mm] "Chip Capacitor, 2-Leads, Body 3.25x1.60mm, IPC Medium Density"
  rect 1.3x1.8 smd: 1(-1.45,0) 2(1.45,0)
  silkscreen extent -2.38,-1.13 2.38,1.13, body extent -1.6,-0.81 1.6,0.81, height 1.62
"CAP 1206/3216 - 0.8MM" [mm] "Chip Capacitor, 2-Leads, Body 3.25x1.60mm, IPC Medium Density"
  rect 1.3x1.8 smd: 1(-1.45,0) 2(1.45,0)
  silkscreen extent -2.37,-1.13 2.38,1.13, body extent -1.6,-0.8 1.6,0.8, height 0.8
"CAP 1210/3225 - 1MM" [mm] "Chip Capacitor, 2-Leads, Body 3.20x2.50mm, IPC Medium Density"
  rect 1.3x2.7 smd: 1(-1.4,0) 2(1.4,0)
  silkscreen extent -2.38,-1.62 2.38,1.62, body extent -1.6,-1.25 1.6,1.25, height 1
"CAP POL 2917/7343" [mm] "Molded Capacitor, 2-Leads, Body 7.30x4.30mm, IPC Medium Density"
  rect 2.55x2.45 smd: 1(-3.025,0) 2(3.025,0)
  silkscreen extent -4.57,-2.3 3.8,2.3, body extent -3.65,-2.15 3.65,2.15, height 4.1
"CASE 457" [mil] "CASE 457-04, MBRM140T1G"
  rect 105.12x100 smd: 1(-65.06,0)
  rect 30x50 smd: 2(27.5,0)
  silkscreen extent -126,-61 -122,-57, body extent -118,-52 27,53, height 43
CDCM1802RGTT [mm] "PQFN, 16-Leads, Body 3,00x3,00mm, Pitch 0,50mm, Thermal Pad 1,45x1,45mm, IPC High Density"
  rect 0.6x0.24 smd: 1(-1.4,0.75) 2(-1.4,0.25) 3(-1.4,-0.25) 4(-1.4,-0.75) 9(1.4,-0.75) 10(1.4,-0.25) 11(1.4,0.25) 12(1.4,0.75)
  rect 0.24x0.6 smd: 5(-0.75,-1.4) 6(-0.25,-1.4) 7(0.25,-1.4) 8(0.75,-1.4) 13(0.75,1.4) 14(0.25,1.4) 15(-0.25,1.4) 16(-0.75,1.4)
  rect 1.45x1.45 smd paste-0.11: 17(0,0)
  silkscreen extent -2.32,-1.55 1.55,1.55, body extent -1.55,-1.55 1.55,1.55, height 1
CDRH4D28NP [mm] "Precision Wire Wound Inductor, 2-Leads, Body 4,70x4,70mm, IPC High Density"
  rect 1.9x5.3 smd: 1(-1.7,0) 2(1.7,0)
  body extent -2.45,-2.35 2.45,2.35, height 3.1
CDRH5D28 [mm] "CDRH5D28 , Precision Wire Wound Inductor, 2-Leads, Body 6,00x6,00mm, IPC High Density"
  rect 2.15x6.3 smd: 1(-2.075,0) 2(2.075,0)
  silkscreen extent -0.45,-3 0.45,3, body extent -3.1,-3.15 3.1,3.15, height 3.1
Crystal [mm]
  round 1.2 hole 0.6: 1(0,0) 2(4.88,0)
  silkscreen extent -3.81,-1.91 8.69,1.91
CVCO55CW [mm]
  rect 1.32x1.32 smd: 1(0,9.779) 2(0,7.239) 3(0,4.699) 4(0,2.159) 5(2.667,0) 6(5.207,0) 7(7.747,0) 8(10.287,0) 9(12.7,3.048) 10(12.7,5.588) 11(12.7,8.128) 12(12.7,10.668) 13(10.541,12.7) 14(8.001,12.7) 15(5.461,12.7) 16(2.921,12.7)
  silkscreen extent -1.95,0 12.7,12.7
DAC1220 [mm]
  rect 1.6x0.41 smd: 1(-2.667,2.235) 2(-2.667,1.6) 3(-2.667,0.965) 4(-2.667,0.33) 5(-2.667,-0.305) 6(-2.667,-0.94) 7(-2.667,-1.575) 8(-2.667,-2.21) 9(2.667,-2.21) 10(2.667,-1.575) 11(2.667,-0.94) 12(2.667,-0.305) 13(2.667,0.33) 14(2.667,0.965) 15(2.667,1.6) 16(2.667,2.235)
  silkscreen extent -1.55,-2.49 1.55,2.49
"DF005S2 - DF10S2" [mm] "4-LEAD, SDIP, 6.5 MM WIDE"
  rect 1.5x1.3 smd: 1(-4.45,2.55) 2(-4.45,-2.55) 3(4.45,-2.55) 4(4.45,2.55)
  silkscreen extent -4.57,-4.25 2.85,4.25, body extent -4.92,-4.25 4.92,4.25, height 2.6
DFLS1100 [mm] "Molded Diode, 2-Leads, Body 2,80x1,78mm, IPC High Density"
  rect 1.05x1.5 smd: 1(-0.85,0)
  rect 2.4x1.5 smd: 2(1.524,0)
  silkscreen extent -0.81,-1.02 1.27,1.07, body extent -1.02,-0.96 2.42,0.96, height 1
DP83867E [mm] "VQFN, 48-Leads, Body 7,00x7,00mm, Pitch 0,50mm, Thermal Pad 4,10x4,10mm, IPC High Density"
  oval 0.6x0.24 smd: 1(-3.4,2.75) 2(-3.4,2.25) 3(-3.4,1.75) 4(-3.4,1.25) 5(-3.4,0.75) 6(-3.4,0.25) 7(-3.4,-0.25) 8(-3.4,-0.75) 9(-3.4,-1.25) 10(-3.4,-1.75) 11(-3.4,-2.25) 12(-3.4,-2.75) 25(3.4,-2.75) 26(3.4,-2.25) 27(3.4,-1.75) 28(3.4,-1.25) 29(3.4,-0.75) 30(3.4,-0.25) 31(3.4,0.25) 32(3.4,0.75) 33(3.4,1.25) 34(3.4,1.75) 35(3.4,2.25) 36(3.4,2.75)
  oval 0.24x0.6 smd: 13(-2.75,-3.4) 14(-2.25,-3.4) 15(-1.75,-3.4) 16(-1.25,-3.4) 17(-0.75,-3.4) 18(-0.25,-3.4) 19(0.25,-3.4) 20(0.75,-3.4) 21(1.25,-3.4) 22(1.75,-3.4) 23(2.25,-3.4) 24(2.75,-3.4) 37(2.75,3.4) 38(2.25,3.4) 39(1.75,3.4) 40(1.25,3.4) 41(0.75,3.4) 42(0.25,3.4) 43(-0.25,3.4) 44(-0.75,3.4) 45(-1.25,3.4) 46(-1.75,3.4) 47(-2.25,3.4) 48(-2.75,3.4)
  rect 4.1x4.1 smd paste-2.5: 49(0,0)
  silkscreen extent -4.35,-3.57 3.57,3.58, body extent -3.57,-3.58 3.58,3.57, height 1
ECS-120-8-33-RWY-TR [mm] "Ceramic package 4-Leads, Body 2,50x3,20mm, Pitch 1,80mm, IPC High Density"
  rect 1.3x1.1 smd: 1(-1.15,-0.9) 2(1.15,-0.9) 3(1.15,0.9) 4(-1.15,0.9)
  silkscreen extent -2.1,-1.55 -2,-1.45, body extent -1.6,-1.25 1.6,1.25, height 0.8
ESDCAN02-2BWY [mm] "SOT23, 3-Leads, Body 2,00x2,10mm, Pitch 0,65mm, IPC High Density"
  rect 0.7x0.42 smd: 1(-1,0.65) 2(-1,-0.65) 3(1,0)
  silkscreen extent -1.12,-1.1 0.67,1.53, body extent -1.3,-1.1 1.3,1.1, height 1.1
FA-23825.0000MB-C3 [mm] "3.2 x 2.5 x 0.7 mm -- FA-238V / FA-238"
  rect 0.8x0.9 smd: 1(-0.75,1.05) 2(-0.75,-1.05) 3(0.75,-1.05) 4(0.75,1.05)
  silkscreen extent -1.81,1.66 -1.71,1.76, body extent -1.25,-1.6 1.25,1.6, height 0.7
